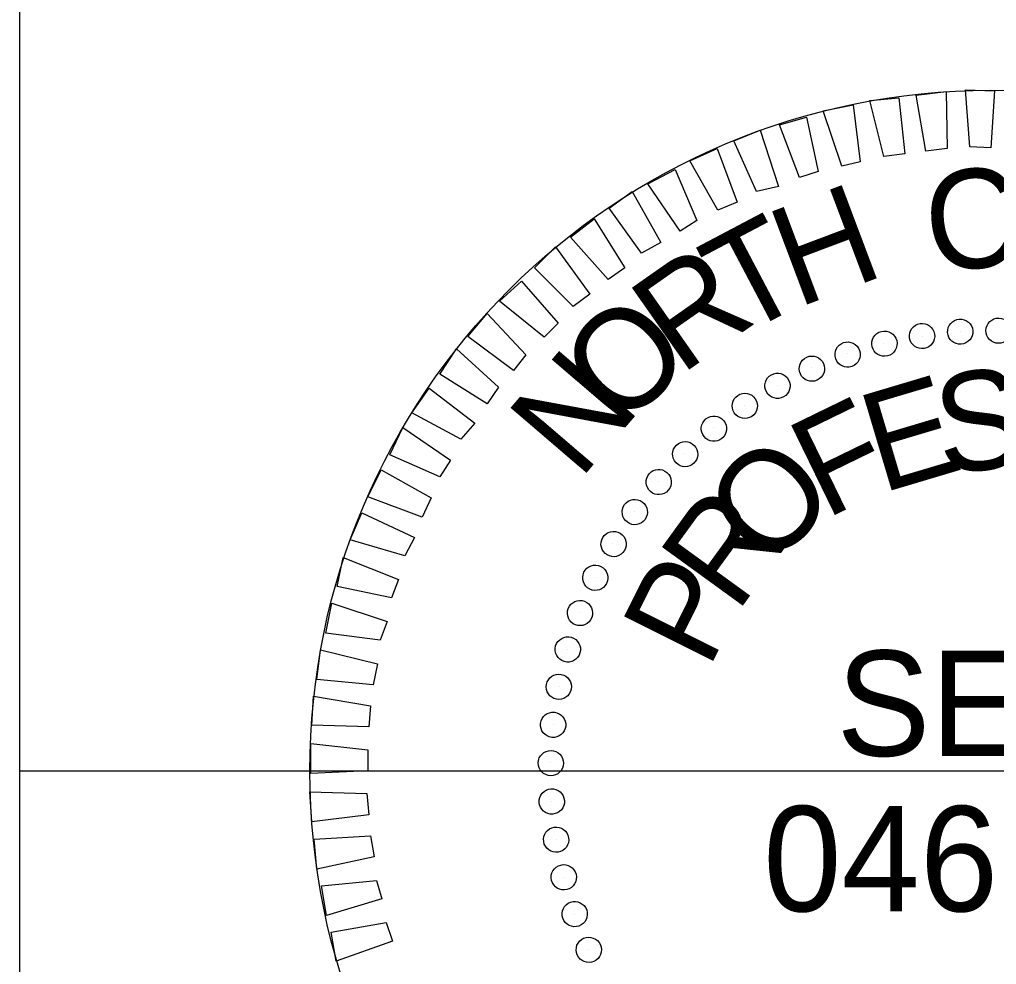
# Model space of a CAD drawing. Extents: x 1184121 to 1184397, y 1246506 to 1246661.
# Drawn here: x 1184344.34 to 1184351.43, y 1246631.22 to 1246638.07 of the extents above; entities that cross this region are included whole.
import ezdxf

# ---------------------------------------------------------------- set-up
doc = ezdxf.new("R2010")
doc.units = 0
for name, color, linetype in [('Scratch_Level_3', 7, 'Continuous'), ('Sheet PE Seal Cell', 7, 'Continuous'), ('Sheet Plan CELL', 7, 'Continuous')]:
    doc.layers.add(name, color=color, linetype=linetype)

msp = doc.modelspace()

# ---------------------------------------------------------------- linework, layer by layer
at = {"layer": 'Scratch_Level_3'}
msp.add_line((1184358.4219, 1246632.6201), (1184344.3472, 1246632.6204), dxfattribs=at)
msp.add_circle((1184351.3846, 1246632.6203), 4.9351, dxfattribs=at)
at = {"layer": 'Sheet PE Seal Cell'}
for p, q in [((1184350.8906, 1246635.7712), (1184350.8906, 1246635.7712)), ((1184351.1641, 1246635.8094), (1184351.1641, 1246635.8094)), ((1184350.6107, 1246635.7203), (1184350.6107, 1246635.7203)), ((1184350.3435, 1246635.644), (1184350.3435, 1246635.644)), ((1184350.089, 1246635.5422), (1184350.089, 1246635.5422)), ((1184349.8409, 1246635.415), (1184349.8409, 1246635.415)), ((1184349.5991, 1246635.2686), (1184349.5991, 1246635.2686)), ((1184349.3764, 1246635.1096), (1184349.3764, 1246635.1096)), ((1184349.1665, 1246634.9187), (1184349.1665, 1246634.9187)), ((1184348.9756, 1246634.7215), (1184348.9756, 1246634.7215)), ((1184348.8038, 1246634.4988), (1184348.8038, 1246634.4988)), ((1184348.6448, 1246634.2698), (1184348.6448, 1246634.2698)), ((1184348.5176, 1246634.0217), (1184348.5176, 1246634.0217)), ((1184348.403, 1246633.7672), (1184348.403, 1246633.7672)), ((1184348.314, 1246633.5), (1184348.314, 1246633.5)), ((1184348.2567, 1246633.2328), (1184348.2567, 1246633.2328)), ((1184348.2122, 1246632.9592), (1184348.2122, 1246632.9592)), ((1184348.1931, 1246632.6793), (1184348.1931, 1246632.6793)), ((1184351.3868, 1246632.622), (1184351.3868, 1246632.622)), ((1184348.1995, 1246632.3994), (1184348.1995, 1246632.3994)), ((1184348.2376, 1246632.1258), (1184348.2376, 1246632.1258)), ((1184348.2885, 1246631.8459), (1184348.2885, 1246631.8459)), ((1184348.3649, 1246631.5787), (1184348.3649, 1246631.5787)), ((1184348.4667, 1246631.3242), (1184348.4667, 1246631.3242))]:
    msp.add_line(p, q, dxfattribs=at)
for points in [[(1184350.916, 1246637.1136), (1184350.846, 1246637.5208), (1184351.0624, 1246637.5462), (1184351.0687, 1246637.1327)], [(1184351.2341, 1246637.1454), (1184351.2023, 1246637.5589), (1184351.4123, 1246637.5526), (1184351.3868, 1246637.1391)], [(1184350.3053, 1246637.0055), (1184350.1717, 1246637.4063), (1184350.388, 1246637.4508), (1184350.4389, 1246637.0373)], [(1184350.6107, 1246637.0754), (1184350.5089, 1246637.4826), (1184350.7188, 1246637.5017), (1184350.7633, 1246637.0945)], [(1184349.9999, 1246636.9227), (1184349.8536, 1246637.3045), (1184350.0508, 1246637.3617), (1184350.1335, 1246636.9673)], [(1184349.6882, 1246636.821), (1184349.5228, 1246637.19), (1184349.7136, 1246637.2663), (1184349.8472, 1246636.8591)], [(1184349.4082, 1246636.6874), (1184349.2047, 1246637.0436), (1184349.4019, 1246637.1327), (1184349.5482, 1246636.7446)], [(1184349.1347, 1246636.5347), (1184348.8993, 1246636.8782), (1184349.0965, 1246636.98), (1184349.2556, 1246636.611)], [(1184348.8547, 1246636.3756), (1184348.6194, 1246636.7001), (1184348.7848, 1246636.821), (1184348.9947, 1246636.452)], [(1184348.613, 1246636.1848), (1184348.3394, 1246636.4901), (1184348.5112, 1246636.6237), (1184348.7339, 1246636.2675)], [(1184348.3585, 1246635.9875), (1184348.0786, 1246636.2675), (1184348.2313, 1246636.4202), (1184348.4794, 1246636.0766)], [(1184348.1486, 1246635.7649), (1184347.8241, 1246636.0257), (1184347.9832, 1246636.172), (1184348.2504, 1246635.8667)], [(1184347.9259, 1246635.5231), (1184347.5951, 1246635.7712), (1184347.735, 1246635.9366), (1184348.015, 1246635.6376)], [(1184347.735, 1246635.2814), (1184347.3915, 1246635.4977), (1184347.5124, 1246635.6822), (1184347.8177, 1246635.4022)], [(1184347.5442, 1246635.0269), (1184347.1879, 1246635.2177), (1184347.3151, 1246635.3959), (1184347.646, 1246635.1414)], [(1184347.3915, 1246634.7533), (1184347.0289, 1246634.9124), (1184347.1243, 1246635.1096), (1184347.4678, 1246634.8742)], [(1184347.2642, 1246634.4607), (1184346.8698, 1246634.607), (1184346.9652, 1246634.8042), (1184347.3279, 1246634.6006)], [(1184347.137, 1246634.1807), (1184346.7426, 1246634.2952), (1184346.8253, 1246634.4925), (1184347.207, 1246634.3143)], [(1184347.0416, 1246633.8754), (1184346.6471, 1246633.9581), (1184346.6917, 1246634.168), (1184347.0925, 1246634.009)], [(1184346.9589, 1246633.57), (1184346.5644, 1246633.6209), (1184346.609, 1246633.8372), (1184347.0098, 1246633.7036)], [(1184346.908, 1246633.2455), (1184346.5008, 1246633.2837), (1184346.5263, 1246633.5), (1184346.9398, 1246633.3982)], [(1184346.8762, 1246632.9401), (1184346.4626, 1246632.9529), (1184346.4754, 1246633.1628), (1184346.8889, 1246633.0928)], [(1184346.8698, 1246632.622), (1184346.4563, 1246632.603), (1184346.4563, 1246632.8193), (1184346.8698, 1246632.7747)], [(1184346.8762, 1246632.3039), (1184346.4626, 1246632.253), (1184346.4499, 1246632.4694), (1184346.8634, 1246632.4566)], [(1184346.9143, 1246631.9986), (1184346.5008, 1246631.9095), (1184346.4817, 1246632.1258), (1184346.8889, 1246632.1513)], [(1184346.9716, 1246631.6932), (1184346.5708, 1246631.5723), (1184346.5326, 1246631.7886), (1184346.9334, 1246631.8268)], [(1184347.0479, 1246631.3878), (1184346.6408, 1246631.2415), (1184346.6026, 1246631.4514), (1184347.0034, 1246631.5214)]]:
    msp.add_lwpolyline(points, close=True, dxfattribs=at)
for centre, major_axis in [((1184351.1642, 1246635.8054), (-0.0064, 0.0914)), ((1184351.4425, 1246635.8127), (0.0016, 0.0916)), ((1184350.8876, 1246635.7739), (-0.0143, 0.0905)), ((1184350.6148, 1246635.7184), (-0.0222, 0.0889)), ((1184350.3479, 1246635.6394), (-0.0298, 0.0866)), ((1184350.0889, 1246635.5373), (-0.0373, 0.0837)), ((1184349.8397, 1246635.4131), (-0.0444, 0.0801)), ((1184349.6023, 1246635.2676), (-0.0512, 0.076)), ((1184349.3785, 1246635.1021), (-0.0577, 0.0712)), ((1184349.17, 1246634.9176), (-0.0636, 0.0659)), ((1184348.9784, 1246634.7156), (-0.0691, 0.0601)), ((1184348.8051, 1246634.4978), (-0.0741, 0.0538)), ((1184348.6514, 1246634.2656), (-0.0785, 0.0472)), ((1184348.5186, 1246634.021), (-0.0823, 0.0402)), ((1184348.4076, 1246633.7657), (-0.0855, 0.0328)), ((1184348.3193, 1246633.5016), (-0.0881, 0.0253)), ((1184348.2543, 1246633.2309), (-0.0899, 0.0175)), ((1184348.2131, 1246632.9556), (-0.0911, 0.0096)), ((1184348.1961, 1246632.6777), (-0.0916, 0.0016)), ((1184348.2034, 1246632.3994), (-0.0914, -0.0064)), ((1184348.2349, 1246632.1228), (-0.0905, -0.0143)), ((1184348.2904, 1246631.85), (-0.0889, -0.0222)), ((1184348.3695, 1246631.5831), (-0.0866, -0.0298)), ((1184348.4715, 1246631.3241), (-0.0837, -0.0373))]:
    msp.add_ellipse(centre, major_axis=major_axis, ratio=0.999708, dxfattribs=at)
at = {"layer": 'Sheet Plan CELL'}
msp.add_line((1184344.3445, 1246508.8745), (1184344.348, 1246657.3636), dxfattribs=at)

# ---------------------------------------------------------------- texts
at = {"layer": 'Sheet PE Seal Cell'}
for s, height, rotation, p in [('C', 0.7178, 6.21987, (1184350.9478, 1246636.2293)), ('H', 0.7212, 20.61948, (1184349.9808, 1246635.9748)), ('T', 0.7232, 27.81977, (1184349.5673, 1246635.7649)), ('R', 0.7247, 35.02051, (1184349.1347, 1246635.4849)), ('O', 0.7254, 42.22174, (1184348.6957, 1246635.0905)), ('N', 0.7251, 49.4235, (1184348.403, 1246634.7215)), ('S', 0.7179, 7.25561, (1184351.0305, 1246634.766)), ('E', 0.72, 16.61107, (1184350.5916, 1246634.6324)), ('F', 0.7226, 25.96703, (1184350.1844, 1246634.4416)), ('O', 0.7254, 44.68124, (1184349.7645, 1246634.0662)), ('R', 0.7245, 54.03965, (1184349.5418, 1246633.7545)), ('P', 0.7224, 63.39889, (1184349.3383, 1246633.3473)), ('SEAL', 0.76321, 360, (1184350.2672, 1246632.73))]:
    msp.add_text(s, height=height, rotation=rotation, dxfattribs=at).set_placement(p)
msp.add_text('046981', height=0.76321, dxfattribs=at).set_placement((1184349.7364, 1246631.6031))

doc.saveas('drawing.dxf')
